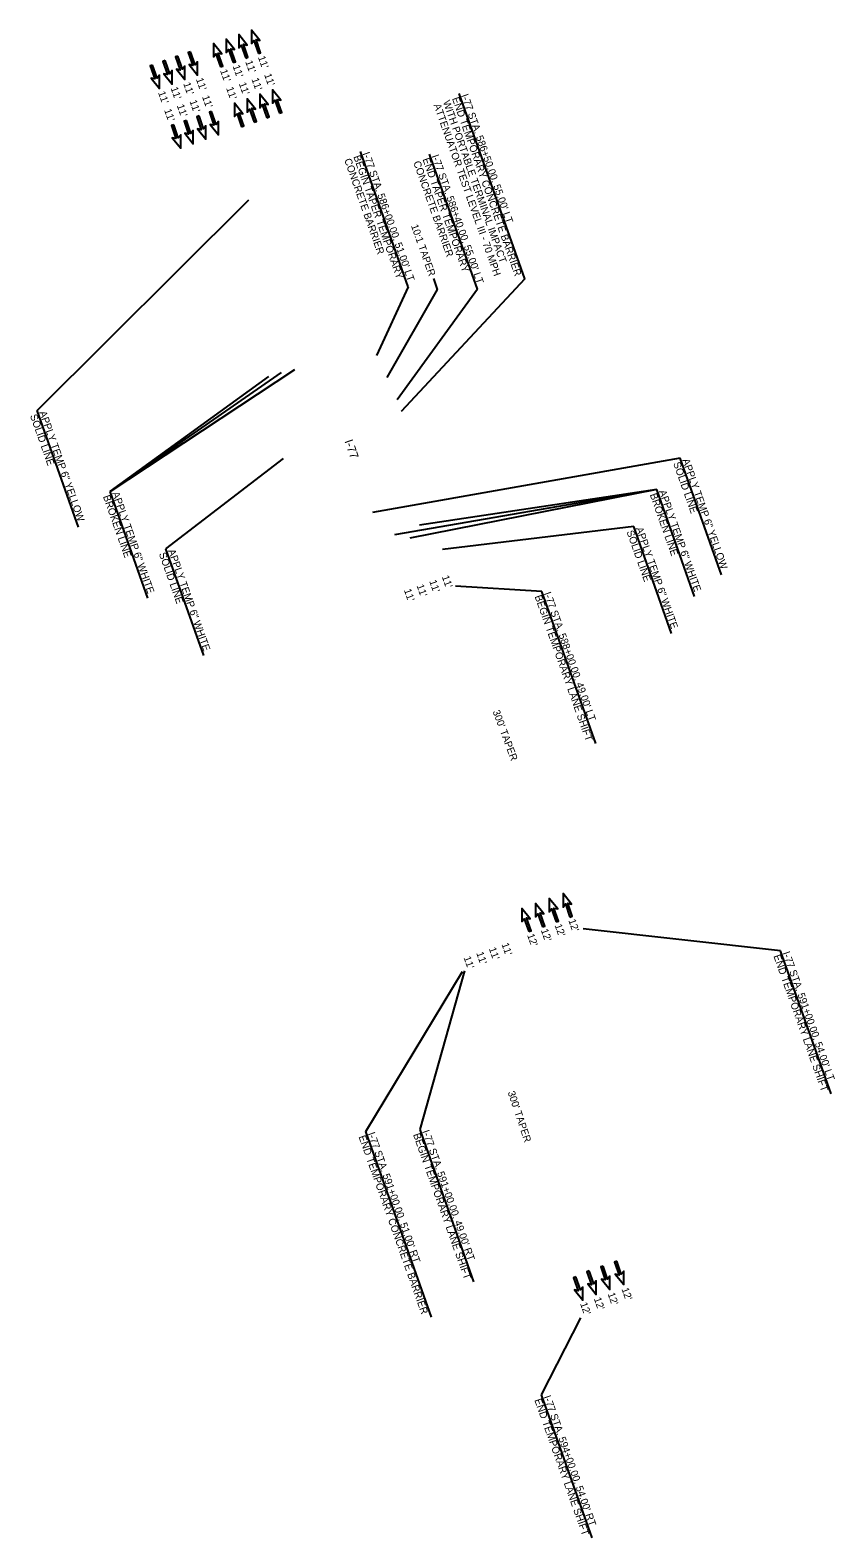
# Model space of a CAD drawing. Extents: x 2004770 to 2007199, y 1133765 to 1140032.
# Drawn here: x 2006539 to 2007199, y 1133765 to 1135002 of the extents above; entities that cross this region are included whole.
import ezdxf

# ---------------------------------------------------------------- set-up
doc = ezdxf.new("R2010")
doc.units = 0
doc.layers.add('RD_PD_MedBWall', color=7, linetype='Continuous')
doc.layers.add('RD_XS_Base', color=7, linetype='Continuous')

msp = doc.modelspace()

# ---------------------------------------------------------------- linework, layer by layer
at = {"layer": 'RD_PD_MedBWall'}
for p, q in [((2006944.8, 1134798.1), (2006891, 1134950.2)), ((2006849.3, 1134791.7), (2006810, 1134902.6)), ((2006906, 1134789.6), (2006866.8, 1134900.5)), ((2006604.5, 1134623.7), (2006756.1, 1134723.8)), ((2006604.5, 1134623.7), (2006745.2, 1134721.4)), ((2006578.5, 1134594.5), (2006544.7, 1134690.1)), ((2007106.3, 1134555.4), (2007072.5, 1134651)), ((2006635.5, 1134536.2), (2006604.5, 1134623.8)), ((2007053.3, 1134625.3), (2006850.6, 1134585.4)), ((2007053.3, 1134625.3), (2006858.6, 1134596)), ((2007084.3, 1134537.7), (2007053.3, 1134625.3)), ((2007065.3, 1134507.3), (2007034.3, 1134594.9)), ((2006681.4, 1134489.2), (2006650.4, 1134576.8)), ((2007003.1, 1134416.9), (2006958.9, 1134541.8)), ((2007196.3, 1134129.7), (2007154.9, 1134246.9)), ((2006868.2, 1133946.6), (2006814.4, 1134098.7)), ((2006903.2, 1133975.5), (2006859, 1134100.4)), ((2007000.1, 1133765.5), (2006958.6, 1133882.7))]:
    msp.add_line(p, q, dxfattribs=at)
for points in [[(2006705.5, 1134975.6), (2006707.4, 1134976.2), (2006703.6, 1134986.9), (2006706.7, 1134986.2), (2006699.8, 1134994.8), (2006699.7, 1134983.8), (2006701.7, 1134986.3)], [(2006715.9, 1134979.2), (2006717.7, 1134979.9), (2006714, 1134990.6), (2006717, 1134989.9), (2006710.1, 1134998.4), (2006710.1, 1134987.5), (2006712.1, 1134989.9)], [(2006726.2, 1134982.9), (2006728.1, 1134983.6), (2006724.3, 1134994.3), (2006727.4, 1134993.6), (2006720.5, 1135002.1), (2006720.5, 1134991.1), (2006722.4, 1134993.6)], [(2006670.5, 1134984.4), (2006668.6, 1134983.8), (2006672.4, 1134973.1), (2006669.4, 1134973.8), (2006676.3, 1134965.2), (2006676.3, 1134976.2), (2006674.3, 1134973.7)], [(2006695.1, 1134971.9), (2006697, 1134972.6), (2006693.2, 1134983.3), (2006696.3, 1134982.6), (2006689.4, 1134991.1), (2006689.4, 1134980.1), (2006691.3, 1134982.6)], [(2006639.4, 1134973.4), (2006637.5, 1134972.7), (2006641.3, 1134962.1), (2006638.2, 1134962.7), (2006645.1, 1134954.2), (2006645.2, 1134965.2), (2006643.2, 1134962.7)], [(2006649.8, 1134977.1), (2006647.9, 1134976.4), (2006651.7, 1134965.7), (2006648.6, 1134966.4), (2006655.5, 1134957.9), (2006655.5, 1134968.9), (2006653.6, 1134966.4)], [(2006660.2, 1134980.8), (2006658.3, 1134980.1), (2006662.1, 1134969.4), (2006659, 1134970.1), (2006665.9, 1134961.6), (2006665.9, 1134972.5), (2006663.9, 1134970.1)], [(2006722.8, 1134926.6), (2006724.7, 1134927.3), (2006720.9, 1134938), (2006724, 1134937.3), (2006717.1, 1134945.8), (2006717.1, 1134934.8), (2006719, 1134937.3)], [(2006733.2, 1134930.3), (2006735.1, 1134930.9), (2006731.3, 1134941.6), (2006734.3, 1134941), (2006727.4, 1134949.5), (2006727.4, 1134938.5), (2006729.4, 1134941)], [(2006743.5, 1134934), (2006745.4, 1134934.6), (2006741.6, 1134945.3), (2006744.7, 1134944.6), (2006737.8, 1134953.1), (2006737.8, 1134942.2), (2006739.8, 1134944.6)], [(2006687.8, 1134935.5), (2006686, 1134934.8), (2006689.7, 1134924.1), (2006686.7, 1134924.8), (2006693.6, 1134916.3), (2006693.6, 1134927.2), (2006691.6, 1134924.8)], [(2006712.4, 1134922.9), (2006714.3, 1134923.6), (2006710.5, 1134934.3), (2006713.6, 1134933.6), (2006706.7, 1134942.1), (2006706.7, 1134931.2), (2006708.7, 1134933.6)], [(2006656.7, 1134924.5), (2006654.9, 1134923.8), (2006658.6, 1134913.1), (2006655.6, 1134913.8), (2006662.5, 1134905.3), (2006662.5, 1134916.2), (2006660.5, 1134913.8)], [(2006667.1, 1134928.1), (2006665.2, 1134927.5), (2006669, 1134916.8), (2006665.9, 1134917.5), (2006672.8, 1134908.9), (2006672.8, 1134919.9), (2006670.9, 1134917.4)], [(2006677.5, 1134931.8), (2006675.6, 1134931.1), (2006679.4, 1134920.4), (2006676.3, 1134921.1), (2006683.2, 1134912.6), (2006683.2, 1134923.6), (2006681.3, 1134921.1)], [(2006970.7, 1134270.7), (2006972.6, 1134271.3), (2006968.8, 1134282), (2006971.9, 1134281.3), (2006965, 1134289.9), (2006965, 1134278.9), (2006966.9, 1134281.4)], [(2006982, 1134274.7), (2006983.9, 1134275.3), (2006980.1, 1134286), (2006983.2, 1134285.3), (2006976.3, 1134293.9), (2006976.3, 1134282.9), (2006978.2, 1134285.4)], [(2006948.1, 1134262.7), (2006950, 1134263.3), (2006946.2, 1134274), (2006949.3, 1134273.3), (2006942.4, 1134281.8), (2006942.4, 1134270.9), (2006944.3, 1134273.3)], [(2006959.4, 1134266.7), (2006961.3, 1134267.3), (2006957.5, 1134278), (2006960.6, 1134277.3), (2006953.7, 1134285.9), (2006953.7, 1134274.9), (2006955.6, 1134277.3)], [(2006997.7, 1133984.4), (2006995.9, 1133983.7), (2006999.6, 1133973), (2006996.6, 1133973.7), (2007003.5, 1133965.2), (2007003.5, 1133976.2), (2007001.5, 1133973.7)], [(2007009.1, 1133988.4), (2007007.2, 1133987.7), (2007011, 1133977), (2007007.9, 1133977.7), (2007014.8, 1133969.2), (2007014.8, 1133980.2), (2007012.8, 1133977.7)], [(2007020.4, 1133992.4), (2007018.5, 1133991.7), (2007022.3, 1133981), (2007019.2, 1133981.7), (2007026.1, 1133973.2), (2007026.1, 1133984.2), (2007024.1, 1133981.7)], [(2006986.8, 1133979.5), (2006984.9, 1133978.8), (2006988.7, 1133968.1), (2006985.6, 1133968.8), (2006992.5, 1133960.3), (2006992.5, 1133971.2), (2006990.6, 1133968.8)]]:
    msp.add_lwpolyline(points, close=True, dxfattribs=at)
for points in [[(2006544.7, 1134690.1), (2006718.5, 1134863)], [(2006869.9, 1134798.3), (2006873, 1134789.5), (2006831.6, 1134717.1)], [(2006944.8, 1134798.1), (2006843.5, 1134689.4)], [(2006849.3, 1134791.7), (2006823.1, 1134735.2)], [(2006906, 1134789.6), (2006840.2, 1134698.9)], [(2006604.9, 1134624), (2006734.8, 1134718)], [(2006650.4, 1134576.8), (2006746.9, 1134650.8)], [(2007072.5, 1134651), (2006819.9, 1134606.4)], [(2007053.3, 1134625.3), (2006838, 1134588.2)], [(2007034.3, 1134594.9), (2006877.3, 1134576)], [(2006958.9, 1134541.8), (2006887.9, 1134546)], [(2007154.9, 1134246.9), (2006992.7, 1134264.9)], [(2006814.4, 1134098.7), (2006893.7, 1134229.9)], [(2006859, 1134100.4), (2006895.6, 1134230.5)], [(2006958.6, 1133882.7), (2006990.9, 1133946)]]:
    msp.add_lwpolyline(points, dxfattribs=at)

# ---------------------------------------------------------------- texts
for s, rotation, p in [("11'", 289.482, (2006694.7, 1134968.9)), ("11'", 289.482, (2006705, 1134972.5)), ("11'", 289.482, (2006715.4, 1134976.2)), ("11'", 289.482, (2006725.8, 1134979.9)), ("11'", 289.482, (2006664.5, 1134958.2)), ("11'", 289.482, (2006674.9, 1134961.9)), ("11'", 289.482, (2006710.1, 1134958.2)), ("11'", 289.482, (2006720.5, 1134961.9)), ("11'", 289.482, (2006730.9, 1134965.5)), ("11'", 289.482, (2006643.8, 1134950.9)), ("11'", 289.482, (2006654.1, 1134954.5)), ("11'", 289.482, (2006679.9, 1134947.5)), ("11'", 289.482, (2006699.7, 1134954.5)), ('WITH PORTABLE TERMINAL IMPACT', 289.482, (2006877.6, 1134943.3)), ('END TEMPORARY CONCRETE BARRIER', 289.482, (2006885.1, 1134946)), ("I-77 STA. 586+50.00, 55.00' LT", 289.482, (2006892.6, 1134948.6)), ("11'", 289.482, (2006648.8, 1134936.5)), ("11'", 289.482, (2006659.2, 1134940.2)), ("11'", 289.482, (2006669.6, 1134943.8)), ('ATTENUATOR TEST LEVEL III - 70 MPH', 289.482, (2006870, 1134940.6)), ('CONCRETE BARRIER', 289.482, (2006796.6, 1134895.7)), ('BEGIN TAPER TEMPORARY', 289.482, (2006804.1, 1134898.3)), ("I-77 STA. 586+00.00, 51.00' LT", 289.482, (2006811.7, 1134901)), ('END TAPER TEMPORARY', 289.482, (2006860.9, 1134896.2)), ("I-77 STA. 586+40.00, 55.00' LT", 289.482, (2006868.4, 1134898.9)), ('CONCRETE BARRIER', 289.482, (2006853.3, 1134893.6)), ('10:1 TAPER', 289.482, (2006851.4, 1134841.7)), ('SOLID LINE', 289.482, (2006538.7, 1134685.9)), ('APPLY TEMP 6" YELLOW', 289.482, (2006546.3, 1134688.6)), ('APPLY TEMP 6" YELLOW', 289.482, (2007074.1, 1134649.5)), ('SOLID LINE', 289.482, (2007066.6, 1134646.8)), ('APPLY TEMP 6" WHITE', 289.482, (2007054.9, 1134623.8)), ('BROKEN LINE', 289.482, (2006598.6, 1134619.6)), ('APPLY TEMP 6" WHITE', 289.482, (2006606.1, 1134622.3)), ('BROKEN LINE', 289.482, (2007047.4, 1134621.1)), ('SOLID LINE', 289.482, (2007028.3, 1134590.7)), ('APPLY TEMP 6" WHITE', 289.482, (2007035.9, 1134593.4)), ('APPLY TEMP 6" WHITE', 289.482, (2006652, 1134575.2)), ('SOLID LINE', 289.482, (2006644.5, 1134572.6)), ("11'", 289.482, (2006866.4, 1134550.1)), ("11'", 289.482, (2006876.7, 1134553.8)), ("11'", 289.482, (2006845.6, 1134542.8)), ("11'", 289.482, (2006856, 1134546.5)), ('BEGIN TEMPORARY LANE SHIFT', 289.482, (2006952.9, 1134537.6)), ("I-77 STA. 588+00.00, 49.00' LT", 289.482, (2006960.5, 1134540.2)), ("300' TAPER", 290.4369, (2006918.4, 1134443.3)), ("12'", 289.482, (2006969.3, 1134267.9)), ("12'", 289.482, (2006980.6, 1134271.9)), ("11'", 289.482, (2006925.7, 1134252.4)), ("12'", 289.482, (2006946.7, 1134259.9)), ("12'", 289.482, (2006958, 1134263.9)), ("11'", 289.482, (2006894.6, 1134241.4)), ("11'", 289.482, (2006905, 1134245.1)), ("11'", 289.482, (2006915.3, 1134248.8)), ('END TEMPORARY LANE SHIFT', 289.482, (2007148.9, 1134242.7)), ("I-77 STA. 591+00.00, 54.00' LT", 289.482, (2007156.5, 1134245.3)), ("300' TAPER", 288.5272, (2006930.8, 1134130.9)), ('END TEMPORARY CONCRETE BARRIER', 289.482, (2006808.4, 1134094.5)), ("I-77 STA. 591+00.00, 51.00' RT", 289.482, (2006816, 1134097.1)), ('BEGIN TEMPORARY LANE SHIFT', 289.482, (2006853.1, 1134096.2)), ("I-77 STA. 591+00.00, 49.00' RT", 289.482, (2006860.7, 1134098.9)), ("12'", 289.482, (2007024.2, 1133969.6)), ("12'", 289.482, (2006990.2, 1133957.6)), ("12'", 289.482, (2007001.5, 1133961.6)), ("12'", 289.482, (2007012.8, 1133965.6)), ("I-77 STA. 594+00.00. 54.00' RT", 289.482, (2006960.3, 1133881.2)), ('END TEMPORARY LANE SHIFT', 289.482, (2006952.7, 1133878.5))]:
    msp.add_text(s, height=6, rotation=rotation, dxfattribs=at).set_placement(p)
at = {"layer": 'RD_XS_Base'}
msp.add_text('I-77', height=7, rotation=289.482, dxfattribs=at).set_placement((2006796.8, 1134665))

doc.saveas('drawing.dxf')
